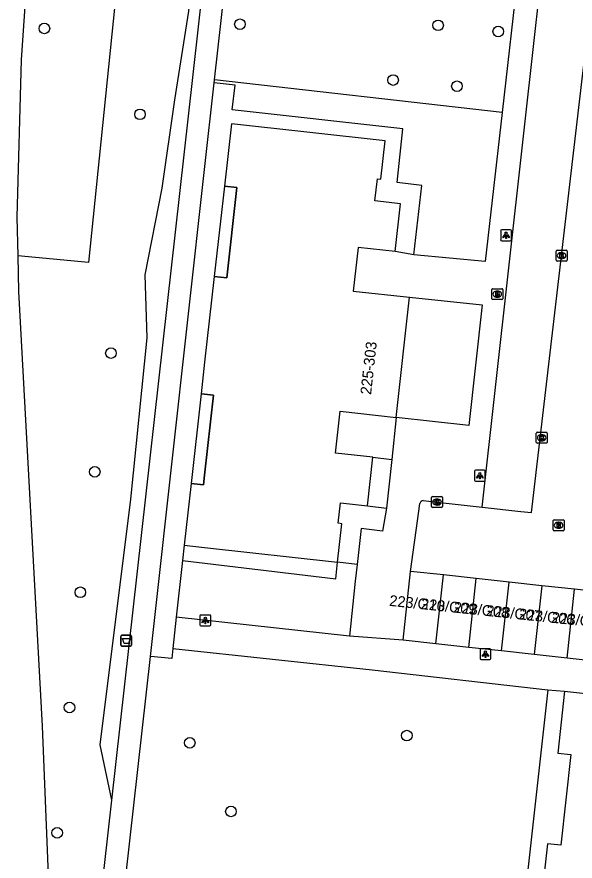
# Model space of a CAD drawing. Extents: x 161928 to 163055, y 386475 to 387428.
# Drawn here: x 161982.7 to 162034.2, y 386644.6 to 386722.4 of the extents above; entities that cross this region are included whole.
import ezdxf

# ---------------------------------------------------------------- set-up
doc = ezdxf.new("R2010")
doc.units = 0
for name, color, linetype in [('IMGEO_Afvalbak', 7, 'Continuous'), ('IMGEO_Berm_groen', 7, 'Continuous'), ('IMGEO_Boom', 7, 'Continuous'), ('IMGEO_Brandkraan', 7, 'Continuous'), ('IMGEO_Fietspad_gesloten', 7, 'Continuous'), ('IMGEO_Groenvoorziening', 7, 'Continuous'), ('IMGEO_Kolk', 7, 'Continuous'), ('IMGEO_Lichtpunt', 7, 'Continuous'), ('IMGEO_Pand', 7, 'Continuous'), ('IMGEO_Pand_nummerreeks', 7, 'Continuous'), ('IMGEO_Pand_overbouw', 7, 'Continuous'), ('IMGEO_Rijbaan_lokaal_open', 7, 'Continuous'), ('IMGEO_Rioolput', 7, 'Continuous'), ('IMGEO_Voetpad_open', 7, 'Continuous')]:
    doc.layers.add(name, color=color, linetype=linetype)

msp = doc.modelspace()

# ---------------------------------------------------------------- linework, layer by layer
at = {"layer": 'IMGEO_Afvalbak'}
for p, q in [((161992.282, 386664.544), (161992.282, 386665.344)), ((161992.282, 386665.344), (161992.282, 386664.544)), ((161992.382, 386665.444), (161993.172, 386665.444)), ((161993.172, 386665.444), (161992.382, 386665.444)), ((161993.272, 386665.344), (161993.272, 386664.544)), ((161993.272, 386664.544), (161993.272, 386665.344)), ((161993.172, 386664.444), (161992.382, 386664.444)), ((161992.382, 386664.444), (161993.172, 386664.444))]:
    msp.add_line(p, q, dxfattribs=at)
msp.add_lwpolyline([(161992.425, 386665.158), (161993.129, 386665.158), (161992.98, 386664.688), (161992.574, 386664.688), (161992.425, 386665.158)], dxfattribs=at)
for centre, start, end in [((161992.382, 386665.344), 90, 180), ((161992.382, 386665.344), 90, 180), ((161993.172, 386665.344), 0, 90), ((161993.172, 386665.344), 360, 90), ((161992.382, 386664.544), 180, 270), ((161992.382, 386664.544), 180, 270), ((161993.172, 386664.544), 270, 0), ((161993.172, 386664.544), 270, 0)]:
    msp.add_arc(centre, 0.1, start, end, dxfattribs=at)
at = {"layer": 'IMGEO_Berm_groen'}
for points in [[(161990.245, 386789.035), (161998.337, 386788.148), (161994.436, 386750), (161989.301, 386699.795), (161982.763, 386700.414)], [(162005.008, 386788.518), (161998.505, 386722.956), (161997.23, 386714.781), (161996.045, 386706.635), (161994.485, 386698.645), (161994.672, 386692.84), (161993.174, 386677.984), (161990.334, 386655.356), (161991.413, 386650.255)]]:
    msp.add_lwpolyline(points, dxfattribs=at)
at = {"layer": 'IMGEO_Boom'}
for centre in [(161985.225, 386721.356), (162003.263, 386721.744), (162021.54, 386721.644), (162027.088, 386721.072), (162017.387, 386716.603), (162023.278, 386716.03), (161994.042, 386713.442), (161991.366, 386691.445), (161989.871, 386680.503), (161988.542, 386669.407), (161987.543, 386658.793), (162018.656, 386656.203), (161998.633, 386655.536), (162002.433, 386649.217), (161986.403, 386647.24)]:
    msp.add_circle(centre, 0.489, dxfattribs=at)
at = {"layer": 'IMGEO_Brandkraan'}
for p, q in [((162026.495, 386696.453), (162026.495, 386697.305)), ((162026.57, 386697.379), (162027.422, 386697.379)), ((162026.983, 386697.159), (162027.008, 386697.159)), ((162027.496, 386697.305), (162027.496, 386696.453)), ((162027.422, 386696.379), (162026.57, 386696.379)), ((162027.006, 386696.599), (162026.981, 386696.599))]:
    msp.add_line(p, q, dxfattribs=at)
for points in [[(162026.495, 386696.453), (162026.495, 386697.305)], [(162026.57, 386697.379), (162027.422, 386697.379)], [(162026.843, 386697.079), (162026.843, 386696.679), (162027.056, 386696.679)], [(162027.074, 386697.079), (162026.843, 386697.079)], [(162027.022, 386696.998), (162026.968, 386696.998), (162026.968, 386696.922)], [(162026.968, 386696.922), (162027.021, 386696.922)], [(162027.03, 386696.846), (162026.968, 386696.846), (162026.968, 386696.765)], [(162026.968, 386696.765), (162027.03, 386696.765)], [(162027.496, 386697.305), (162027.496, 386696.453)], [(162027.422, 386696.379), (162026.57, 386696.379)]]:
    msp.add_lwpolyline(points, dxfattribs=at)
for centre, radius, start, end in [((162026.572, 386697.303), 0.0765, 91.55205, 178.44795), ((162026.572, 386697.303), 0.0765, 91.55205, 178.44795), ((162027.023, 386696.96), 0.0379, 267.82845, 90.93552), ((162027.031, 386696.805), 0.0404, 269.87594, 90.50774), ((162027.078, 386696.934), 0.145, 59.4692, 91.53667), ((162027.103, 386696.981), 0.0922, 285.51372, 58.15012), ((162027.108, 386696.789), 0.105, 301.31148, 78.98903), ((162027.42, 386697.303), 0.0765, 1.55205, 88.44795), ((162027.42, 386697.303), 0.0765, 1.55205, 88.44795), ((162026.572, 386696.455), 0.0765, 181.55205, 268.44795), ((162026.572, 386696.455), 0.0765, 181.55205, 268.44795), ((162027.062, 386696.93), 0.251, 268.66757, 293.53466), ((162027.42, 386696.455), 0.0765, 271.55205, 358.44795), ((162027.42, 386696.455), 0.0765, 271.55205, 358.44795)]:
    msp.add_arc(centre, radius, start, end, dxfattribs=at)
for centre, major_axis, ratio, start_param, end_param in [((162026.982, 386696.879), (-0.387, 0.002), 0.722429, 4.712389, 7.853982), ((162027.007, 386696.879), (-0.39, 0.002), 0.717154, 1.570796, 4.712389)]:
    msp.add_ellipse(centre, major_axis=major_axis, ratio=ratio, start_param=start_param, end_param=end_param, dxfattribs=at)
at = {"layer": 'IMGEO_Fietspad_gesloten'}
for points in [[(161990.245, 386789.035), (161985.832, 386750), (161984.098, 386733.266), (161983.074, 386718.473), (161982.687, 386703.955), (161982.763, 386700.414)], [(161982.763, 386700.414), (161982.834, 386697.131), (161985.017, 386657.078), (161986.078, 386631.198), (161986.407, 386623.174), (161986.323, 386614.553)]]:
    msp.add_lwpolyline(points, dxfattribs=at)
at = {"layer": 'IMGEO_Groenvoorziening'}
for points in [[(162027.442, 386713.619), (162000.921, 386716.619)], [(162031.664, 386660.431), (162027.344, 386621.709)]]:
    msp.add_lwpolyline(points, dxfattribs=at)
at = {"layer": 'IMGEO_Kolk'}
for p, q in [((162032.433, 386699.998), (162032.433, 386700.85)), ((162032.508, 386700.924), (162033.36, 386700.924)), ((162032.921, 386700.704), (162032.946, 386700.704)), ((162033.434, 386700.85), (162033.434, 386699.998)), ((162033.36, 386699.924), (162032.508, 386699.924)), ((162032.944, 386700.144), (162032.919, 386700.144)), ((162030.599, 386683.218), (162030.599, 386684.07)), ((162030.674, 386684.144), (162031.526, 386684.144)), ((162031.087, 386683.924), (162031.112, 386683.924)), ((162031.6, 386684.07), (162031.6, 386683.218)), ((162031.526, 386683.144), (162030.674, 386683.144)), ((162031.11, 386683.364), (162031.085, 386683.364)), ((162020.94, 386677.296), (162020.94, 386678.148)), ((162021.015, 386678.222), (162021.867, 386678.222)), ((162021.941, 386678.148), (162021.941, 386677.296)), ((162021.451, 386677.442), (162021.426, 386677.442)), ((162021.428, 386678.002), (162021.453, 386678.002)), ((162021.867, 386677.222), (162021.015, 386677.222))]:
    msp.add_line(p, q, dxfattribs=at)
for points in [[(162032.433, 386699.998), (162032.433, 386700.85)], [(162032.508, 386700.924), (162033.36, 386700.924)], [(162033.434, 386700.85), (162033.434, 386699.998)], [(162033.36, 386699.924), (162032.508, 386699.924)], [(162032.754, 386700.624), (162032.877, 386700.624), (162032.877, 386700.473), (162033.007, 386700.624), (162033.171, 386700.624), (162033.025, 386700.473), (162033.178, 386700.224), (162033.026, 386700.224), (162032.941, 386700.388), (162032.877, 386700.321), (162032.877, 386700.224), (162032.754, 386700.224), (162032.754, 386700.624)], [(162030.599, 386683.218), (162030.599, 386684.07)], [(162030.674, 386684.144), (162031.526, 386684.144)], [(162030.92, 386683.844), (162031.043, 386683.844), (162031.043, 386683.693), (162031.173, 386683.844), (162031.337, 386683.844), (162031.191, 386683.693), (162031.344, 386683.444), (162031.192, 386683.444), (162031.107, 386683.608), (162031.043, 386683.541), (162031.043, 386683.444), (162030.92, 386683.444), (162030.92, 386683.844)], [(162031.6, 386684.07), (162031.6, 386683.218)], [(162031.526, 386683.144), (162030.674, 386683.144)], [(162020.94, 386677.296), (162020.94, 386678.148)], [(162021.015, 386678.222), (162021.867, 386678.222)], [(162021.941, 386678.148), (162021.941, 386677.296)], [(162021.261, 386677.922), (162021.384, 386677.922), (162021.384, 386677.771), (162021.514, 386677.922), (162021.678, 386677.922), (162021.532, 386677.771), (162021.685, 386677.522), (162021.533, 386677.522), (162021.448, 386677.686), (162021.384, 386677.619), (162021.384, 386677.522), (162021.261, 386677.522), (162021.261, 386677.922)], [(162021.867, 386677.222), (162021.015, 386677.222)]]:
    msp.add_lwpolyline(points, dxfattribs=at)
for centre, start, end in [((162032.51, 386700.848), 91.55205, 178.44795), ((162032.51, 386700.848), 91.55205, 178.44795), ((162033.358, 386700.848), 1.55205, 88.44795), ((162033.358, 386700.848), 1.55205, 88.44795), ((162032.51, 386700), 181.55205, 268.44795), ((162032.51, 386700), 181.55205, 268.44795), ((162033.358, 386700), 271.55205, 358.44795), ((162033.358, 386700), 271.55205, 358.44795), ((162030.676, 386684.068), 91.55205, 178.44795), ((162030.676, 386684.068), 91.55205, 178.44795), ((162031.524, 386684.068), 1.55205, 88.44795), ((162031.524, 386684.068), 1.55205, 88.44795), ((162030.676, 386683.22), 181.55205, 268.44795), ((162030.676, 386683.22), 181.55205, 268.44795), ((162031.524, 386683.22), 271.55205, 358.44795), ((162031.524, 386683.22), 271.55205, 358.44795), ((162021.017, 386678.146), 91.55205, 178.44795), ((162021.017, 386678.146), 91.55205, 178.44795), ((162021.865, 386678.146), 1.55205, 88.44795), ((162021.865, 386678.146), 1.55205, 88.44795), ((162021.017, 386677.298), 181.55205, 268.44795), ((162021.017, 386677.298), 181.55205, 268.44795), ((162021.865, 386677.298), 271.55205, 358.44795), ((162021.865, 386677.298), 271.55205, 358.44795)]:
    msp.add_arc(centre, 0.0765, start, end, dxfattribs=at)
for centre, major_axis, ratio, start_param, end_param in [((162032.92, 386700.424), (-0.387, 0.002), 0.722429, 4.712389, 7.853982), ((162032.945, 386700.424), (-0.39, 0.002), 0.717154, 1.570796, 4.712389), ((162031.086, 386683.644), (-0.387, 0.002), 0.722429, 4.712389, 7.853982), ((162031.111, 386683.644), (-0.39, 0.002), 0.717154, 1.570796, 4.712389), ((162021.427, 386677.722), (-0.387, 0.002), 0.722429, 4.712389, 7.853982), ((162021.452, 386677.722), (-0.39, 0.002), 0.717154, 1.570796, 4.712389)]:
    msp.add_ellipse(centre, major_axis=major_axis, ratio=ratio, start_param=start_param, end_param=end_param, dxfattribs=at)
at = {"layer": 'IMGEO_Lichtpunt'}
for p, q in [((162027.31, 386702.703), (162027.31, 386701.896)), ((162027.31, 386702.703), (162027.31, 386701.896)), ((162028.212, 386702.798), (162027.404, 386702.798)), ((162028.212, 386702.798), (162027.404, 386702.798)), ((162028.306, 386701.896), (162028.306, 386702.703)), ((162028.306, 386701.896), (162028.306, 386702.703)), ((162027.404, 386701.802), (162028.212, 386701.802)), ((162027.404, 386701.802), (162028.212, 386701.802)), ((162024.893, 386680.558), (162024.893, 386679.751)), ((162024.893, 386680.558), (162024.893, 386679.751)), ((162025.795, 386680.653), (162024.987, 386680.653)), ((162025.795, 386680.653), (162024.987, 386680.653)), ((162025.889, 386679.751), (162025.889, 386680.558)), ((162025.889, 386679.751), (162025.889, 386680.558)), ((162024.987, 386679.657), (162025.795, 386679.657)), ((162024.987, 386679.657), (162025.795, 386679.657)), ((161999.575, 386667.218), (161999.575, 386666.411)), ((161999.575, 386667.218), (161999.575, 386666.411)), ((162000.477, 386667.313), (161999.669, 386667.313)), ((162000.477, 386667.313), (161999.669, 386667.313)), ((162000.571, 386666.411), (162000.571, 386667.218)), ((162000.571, 386666.411), (162000.571, 386667.218)), ((161999.669, 386666.317), (162000.477, 386666.317)), ((161999.669, 386666.317), (162000.477, 386666.317)), ((162025.405, 386664.106), (162025.405, 386663.299)), ((162025.405, 386664.106), (162025.405, 386663.299)), ((162026.307, 386664.201), (162025.499, 386664.201)), ((162026.307, 386664.201), (162025.499, 386664.201)), ((162026.401, 386663.299), (162026.401, 386664.106)), ((162026.401, 386663.299), (162026.401, 386664.106)), ((162025.499, 386663.205), (162026.307, 386663.205)), ((162025.499, 386663.205), (162026.307, 386663.205))]:
    msp.add_line(p, q, dxfattribs=at)
for points in [[(162027.684, 386702.367), (162027.723, 386702.339), (162027.535, 386702.077), (162027.497, 386702.104), (162027.684, 386702.367)], [(162027.786, 386702.319), (162027.833, 386702.319), (162027.833, 386701.997), (162027.786, 386701.997), (162027.786, 386702.319)], [(162027.896, 386702.339), (162027.934, 386702.366), (162028.121, 386702.104), (162028.082, 386702.076), (162027.896, 386702.339)], [(162025.267, 386680.222), (162025.306, 386680.194), (162025.118, 386679.932), (162025.08, 386679.959), (162025.267, 386680.222)], [(162025.369, 386680.174), (162025.416, 386680.174), (162025.416, 386679.852), (162025.369, 386679.852), (162025.369, 386680.174)], [(162025.479, 386680.194), (162025.517, 386680.221), (162025.704, 386679.959), (162025.665, 386679.931), (162025.479, 386680.194)], [(161999.949, 386666.882), (161999.988, 386666.854), (161999.8, 386666.592), (161999.762, 386666.619), (161999.949, 386666.882)], [(162000.051, 386666.834), (162000.098, 386666.834), (162000.098, 386666.512), (162000.051, 386666.512), (162000.051, 386666.834)], [(162000.161, 386666.854), (162000.199, 386666.881), (162000.386, 386666.619), (162000.347, 386666.591), (162000.161, 386666.854)], [(162025.779, 386663.77), (162025.818, 386663.742), (162025.63, 386663.48), (162025.592, 386663.507), (162025.779, 386663.77)], [(162025.881, 386663.722), (162025.928, 386663.722), (162025.928, 386663.4), (162025.881, 386663.4), (162025.881, 386663.722)], [(162025.991, 386663.742), (162026.029, 386663.769), (162026.216, 386663.507), (162026.177, 386663.479), (162025.991, 386663.742)]]:
    msp.add_lwpolyline(points, dxfattribs=at)
for centre in [(162027.809, 386702.501), (162025.392, 386680.356), (162000.074, 386667.016), (162025.904, 386663.904)]:
    msp.add_circle(centre, 0.0994, dxfattribs=at)
for centre, start, end in [((162027.404, 386702.703), 90, 180), ((162027.404, 386702.703), 90, 180), ((162028.212, 386702.703), 0, 90), ((162028.212, 386702.703), 0, 90), ((162027.404, 386701.896), 180, 270), ((162027.404, 386701.896), 180, 270), ((162028.212, 386701.896), 270, 0), ((162028.212, 386701.896), 270, 360), ((162024.987, 386680.558), 90, 180), ((162024.987, 386680.558), 90, 180), ((162025.795, 386680.558), 0, 90), ((162025.795, 386680.558), 0, 90), ((162024.987, 386679.751), 180, 270), ((162024.987, 386679.751), 180, 270), ((162025.795, 386679.751), 270, 0), ((162025.795, 386679.751), 270, 360), ((161999.669, 386667.218), 90, 180), ((161999.669, 386667.218), 90, 180), ((162000.477, 386667.218), 0, 90), ((162000.477, 386667.218), 0, 90), ((161999.669, 386666.411), 180, 270), ((161999.669, 386666.411), 180, 270), ((162000.477, 386666.411), 270, 0), ((162000.477, 386666.411), 270, 360), ((162025.499, 386664.106), 90, 180), ((162025.499, 386664.106), 90, 180), ((162026.307, 386664.106), 0, 90), ((162026.307, 386664.106), 0, 90), ((162025.499, 386663.299), 180, 270), ((162025.499, 386663.299), 180, 270), ((162026.307, 386663.299), 270, 0), ((162026.307, 386663.299), 270, 360)]:
    msp.add_arc(centre, 0.0946, start, end, dxfattribs=at)
at = {"layer": 'IMGEO_Pand'}
for points in [[(162017.593, 386700.805), (162018.081, 386705.198), (162015.711, 386705.461), (162015.939, 386707.505), (162016.265, 386707.468), (162016.658, 386710.996), (162002.47, 386712.573), (162001.83, 386706.814)], [(162001.83, 386706.814), (162002.967, 386706.687), (162002.043, 386698.37), (162000.877, 386698.499)], [(162017.593, 386700.805), (162014.158, 386701.186), (162013.711, 386697.164), (162018.892, 386696.588)], [(162000.877, 386698.499), (162000, 386690.615), (161999.675, 386687.693)], [(162017.662, 386685.516), (162018.892, 386696.588)], [(161999.675, 386687.693), (162000, 386687.657), (162000.821, 386687.566), (162000, 386680.185), (161999.903, 386679.313), (161998.756, 386679.44)], [(162015.528, 386681.841), (162012.067, 386682.225), (162012.497, 386686.09), (162017.662, 386685.516)], [(162015.032, 386677.378), (162015.528, 386681.841)], [(161998.756, 386679.44), (161998.123, 386673.748)], [(162012.262, 386672.176), (162012.656, 386675.725), (162012.33, 386675.762), (162012.54, 386677.655), (162015.032, 386677.378)], [(161998.123, 386673.748), (162000, 386673.539), (162012.262, 386672.176)], [(162018.305, 386664.991), (162018.998, 386671.334)], [(162022.025, 386671.003), (162018.998, 386671.334)], [(162021.332, 386664.66), (162022.025, 386671.003)], [(162025.052, 386670.672), (162022.025, 386671.003)], [(162024.359, 386664.329), (162025.052, 386670.672)], [(162028.079, 386670.342), (162025.052, 386670.672)], [(162027.386, 386663.999), (162028.079, 386670.342)], [(162031.106, 386670.011), (162028.079, 386670.342)], [(162031.106, 386670.011), (162030.413, 386663.668)], [(162034.133, 386669.68), (162031.106, 386670.011)], [(162033.44, 386663.337), (162034.133, 386669.68)], [(162037.161, 386669.349), (162034.133, 386669.68)], [(162021.332, 386664.66), (162018.305, 386664.991)], [(162024.359, 386664.329), (162021.332, 386664.66)], [(162027.386, 386663.999), (162024.359, 386664.329)], [(162030.413, 386663.668), (162027.386, 386663.999)], [(162033.44, 386663.337), (162030.413, 386663.668)], [(162036.467, 386663.006), (162033.44, 386663.337)], [(162033.207, 386660.295), (162032.572, 386654.589), (162033.788, 386654.454), (162032.858, 386646.103), (162031.616, 386646.242), (162030.421, 386635.511), (162031.659, 386635.373), (162030.727, 386626.999), (162029.524, 386627.133), (162028.901, 386621.536)], [(162033.207, 386660.295), (162047.236, 386658.733)]]:
    msp.add_lwpolyline(points, dxfattribs=at)
at = {"layer": 'IMGEO_Pand_overbouw'}
for points in [[(162001.83, 386706.814), (162000.877, 386698.499), (162002.043, 386698.37), (162002.967, 386706.687)], [(161999.675, 386687.693), (161998.756, 386679.44), (161999.903, 386679.313), (162000, 386680.185), (162000.821, 386687.566), (162000, 386687.657)]]:
    msp.add_lwpolyline(points, close=True, dxfattribs=at)
at = {"layer": 'IMGEO_Rijbaan_lokaal_open'}
for points in [[(162025.596, 386677.256), (162029.178, 386676.854), (162030.14, 386676.772), (162035.688, 386724.098)], [(162018.998, 386671.334), (162019.766, 386676.872), (162019.864, 386677.601)], [(162020.162, 386677.862), (162021.441, 386677.722), (162025.596, 386677.256)]]:
    msp.add_lwpolyline(points, dxfattribs=at)
msp.add_arc((162020.174, 386677.548), 0.314, 92.11801, 170.30827, dxfattribs=at)
at = {"layer": 'IMGEO_Rioolput'}
for p, q in [((162032.157, 386675.155), (162032.157, 386676.007)), ((162032.232, 386676.081), (162033.084, 386676.081)), ((162032.645, 386675.861), (162032.67, 386675.861)), ((162033.158, 386676.007), (162033.158, 386675.155)), ((162033.084, 386675.081), (162032.232, 386675.081)), ((162032.668, 386675.301), (162032.643, 386675.301))]:
    msp.add_line(p, q, dxfattribs=at)
for points in [[(162032.157, 386675.155), (162032.157, 386676.007)], [(162032.232, 386676.081), (162033.084, 386676.081)], [(162032.746, 386675.779), (162032.494, 386675.781), (162032.494, 386675.381)], [(162033.158, 386676.007), (162033.158, 386675.155)], [(162033.084, 386675.081), (162032.232, 386675.081)], [(162032.494, 386675.381), (162032.618, 386675.381), (162032.618, 386675.543), (162032.629, 386675.543)], [(162032.672, 386675.7), (162032.618, 386675.7), (162032.618, 386675.619)], [(162032.618, 386675.619), (162032.67, 386675.619)], [(162032.676, 386675.514), (162032.747, 386675.381), (162032.887, 386675.381), (162032.822, 386675.507)]]:
    msp.add_lwpolyline(points, dxfattribs=at)
for centre, radius, start, end in [((162032.234, 386676.005), 0.0765, 91.55205, 178.44795), ((162032.234, 386676.005), 0.0765, 91.55205, 178.44795), ((162032.745, 386675.669), 0.109, 350.36119, 89.41601), ((162033.082, 386676.005), 0.0765, 1.55205, 88.44795), ((162033.082, 386676.005), 0.0765, 1.55205, 88.44795), ((162032.234, 386675.157), 0.0765, 181.55205, 268.44795), ((162032.234, 386675.157), 0.0765, 181.55205, 268.44795), ((162032.628, 386675.49), 0.0533, 26.02933, 88.69889), ((162032.654, 386675.808), 0.19, 274.7715, 282.96867), ((162032.678, 386675.604), 0.0964, 77.00612, 93.18647), ((162032.692, 386675.661), 0.0378, 276.66336, 79.67722), ((162032.743, 386675.669), 0.112, 277.58423, 350.98172), ((162032.727, 386675.454), 0.108, 29.51342, 73.79051), ((162033.082, 386675.157), 0.0765, 271.55205, 358.44795), ((162033.082, 386675.157), 0.0765, 271.55205, 358.44795)]:
    msp.add_arc(centre, radius, start, end, dxfattribs=at)
for centre, major_axis, ratio, start_param, end_param in [((162032.644, 386675.581), (-0.387, 0.002), 0.722429, 4.712389, 7.853982), ((162032.669, 386675.581), (-0.39, 0.002), 0.717154, 1.570796, 4.712389)]:
    msp.add_ellipse(centre, major_axis=major_axis, ratio=ratio, start_param=start_param, end_param=end_param, dxfattribs=at)
at = {"layer": 'IMGEO_Voetpad_open'}
for points in [[(162005.028, 386771.813), (161998.872, 386716.846), (161991.413, 386650.255)], [(162000.921, 386716.619), (162004.653, 386750), (162005.214, 386755.021), (162005.304, 386755.813)], [(162028.943, 386726.903), (162027.442, 386713.619)], [(162025.596, 386677.256), (162030.559, 386721.622), (162030.861, 386724.346)], [(161995.016, 386663.48), (161995.486, 386667.633), (162000, 386708.347), (162000.892, 386716.355)], [(162000.892, 386716.355), (162000.921, 386716.619)], [(162019.314, 386700.509), (162020.04, 386706.893), (162017.75, 386707.17), (162018.281, 386712.103), (162002.552, 386713.863), (162002.809, 386716.141), (162000.892, 386716.355)], [(162027.442, 386713.619), (162025.888, 386699.876), (162019.314, 386700.509)], [(162001.83, 386706.814), (162000.877, 386698.499)], [(162019.314, 386700.509), (162017.593, 386700.805)], [(162018.892, 386696.588), (162025.59, 386695.882), (162024.361, 386684.778), (162017.662, 386685.516)], [(161999.675, 386687.693), (161998.756, 386679.44)], [(162017.662, 386685.516), (162017.269, 386681.642)], [(162015.528, 386681.841), (162017.269, 386681.642)], [(162017.269, 386681.642), (162016.787, 386677.161)], [(162015.032, 386677.378), (162016.787, 386677.161)], [(162016.787, 386677.161), (162016.408, 386675.032), (162014.442, 386675.269), (162014.065, 386671.976)], [(161998.123, 386673.748), (161997.965, 386672.335)], [(161997.965, 386672.335), (161997.381, 386667.106)], [(161997.965, 386672.335), (162012.093, 386670.65), (162012.262, 386672.176)], [(162014.065, 386671.976), (162012.262, 386672.176)], [(162014.065, 386671.976), (162013.902, 386670.434), (162013.368, 386665.349)], [(161997.381, 386667.106), (161997.06, 386664.231)], [(162013.368, 386665.349), (161997.381, 386667.106)], [(162018.305, 386664.991), (162013.368, 386665.349)], [(161997.06, 386664.231), (161996.981, 386663.319), (161995.016, 386663.48)], [(161997.06, 386664.231), (162015.473, 386662.253), (162031.664, 386660.431)], [(161990.684, 386624.497), (161990.807, 386625.964), (161995.016, 386663.48)], [(162031.664, 386660.431), (162033.207, 386660.295)], [(161991.413, 386650.255), (161988.931, 386628.093), (161988.105, 386628.184), (161987.456, 386622.282), (161987.333, 386614.588), (161986.323, 386614.553)]]:
    msp.add_lwpolyline(points, dxfattribs=at)

# ---------------------------------------------------------------- texts
at = {"layer": 'IMGEO_Pand_nummerreeks'}
for s, rotation, p in [('225-303', 83.66094, (162015.355, 386687.573)), ('223/G10', 354.07357, (162017.006, 386668.162)), ('223/G09', 354.07357, (162019.92, 386667.86)), ('223/G08', 354.07357, (162022.936, 386667.547)), ('223/G07', 354.07357, (162025.943, 386667.235)), ('223/G06', 354.07357, (162028.954, 386666.922)), ('223/G05', 354.07357, (162031.964, 386666.61))]:
    msp.add_text(s, height=1, rotation=rotation, dxfattribs=at).set_placement(p)

doc.saveas('drawing.dxf')
